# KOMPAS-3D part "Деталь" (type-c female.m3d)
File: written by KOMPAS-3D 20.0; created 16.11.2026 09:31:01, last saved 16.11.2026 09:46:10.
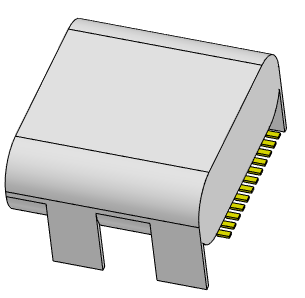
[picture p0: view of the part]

Document properties: Полное имя файла: D:\RicWork\Project-EPS32\box_compas\разъемы\type-c female.m3d

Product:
- Part/product: Деталь
    Масса: 0.00128034
  - Body: Тело 1
      Масса: 0.00127916
  - Body: Тело 2
      Масса: 1.1784e-06

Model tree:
1. Эскиз:1
2. Элемент выдавливания:1
     Расстояние 1 = 7.77
3. Скругление:1  (with: Элемент выдавливания:1)
     Радиус = 1.5
4. Эскиз:2  (with: Элемент выдавливания:1, Скругление:1)
5. Элемент выдавливания:2
     Расстояние 2 = 4
6. Скругление:2  (with: Элемент выдавливания:2)
     Радиус = 0.25
7. Эскиз:3  (with: Элемент выдавливания:1, Скругление:1)
8. Элемент выдавливания:3
     Расстояние 2 = 0.2
9. Смещенная плоскость:1  (with: Элемент выдавливания:1)
     Расстояние = 4.47
10. Зеркальный массив:1
11. Экземпляр ( 1 )
12. Экземпляр ( 2 )  (with: Элемент выдавливания:3)
13. Эскиз:4  (with: Элемент выдавливания:1, Скругление:1)
14. Элемент выдавливания:4
     Расстояние 1 = 0.5
15. Массив по сетке:1  (with: Элемент выдавливания:4, Эскиз:4)  (12 pattern instances)
     Шаг 1 = 0.5; Угол раствора = 90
